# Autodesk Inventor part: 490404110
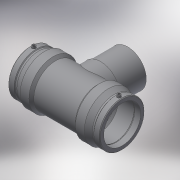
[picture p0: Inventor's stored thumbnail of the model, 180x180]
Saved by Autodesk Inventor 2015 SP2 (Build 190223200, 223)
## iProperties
Created: 2017-06
Part Number: 490404110
Material: Generic
Description: PLASSON TEE 110-110-110
Document SubType Name: Modeling
Designer: KIM
Mass: 2082.26 g
Surface Area: 3178.95 cm^2
Volume: 2082.26 cm^3
Density: 1 g/cm^3
Appearance: Default
Author: KIM
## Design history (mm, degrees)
derived "490404.ipt"
feature "Solid1::490404.ipt"
tag "TaggingFeature1"
body "Solid1"
other parameters: "d0" = 326, "d2" = 143, "d3" = 71, "d4" = 81.5, "d5" = 128.7, "d6" = 104.5, "d8" = 168 deg, "d10" = 28.4, "d11" = 9.46667, "d13" = 326, "d14" = 17.6296, "d17" = 99, "d19" = 3.52592, "d20" = 168 deg, "d22" = 132.99, "d23" = 143, "d24" = 129.0003, "d25" = 135 deg, "d26" = 228.2, "d27" = 135 deg, "d29" = 81, "d30" = 15, "d31" = 130.4, "d34" = 5 deg, "d35" = 15, "d39" = 5 deg, "d40" = 9.6, "d41" = 4.8, "d42" = 6, "d43" = 0, "d45" = 4, "d46" = 14, "d47" = 0, "d51" = 0, "d52" = 88, "d54" = 0, "d55" = 128.7, "d56" = 143, "d57" = 114.1, "d58" = 135 deg, "d59" = 71, "d60" = 71, "d61" = 135 deg, "d72" = 148.33, "d73" = 74.165, "d75" = 115.5, "d77" = 0, "d78" = 88, "d80" = 0, "d82" = 88.5, "d83" = 0, "d84" = 3, "d85" = 0, "d86" = 3, "d87" = 0, "d88" = 20.59, "d89" = 5.1475, "d90" = 20.59, "L_" = 326, "L_1" = 71, "D_" = 143, "A_" = 81, "d_2" = 12
